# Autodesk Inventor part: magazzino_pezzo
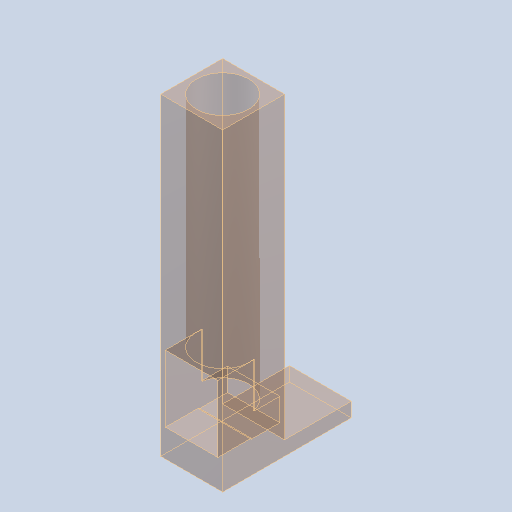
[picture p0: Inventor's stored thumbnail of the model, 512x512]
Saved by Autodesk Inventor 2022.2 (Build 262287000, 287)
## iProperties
Created: 2024-10
Part Number: magazzino_pezzo
Material: Alluminio 6061
Document SubType Name: Modeling
Designer: 18907419
Density: 2.7 g/cm^3
Appearance: Default
Author: 18907419
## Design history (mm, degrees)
feature "Solido1"
node "Solido2"
